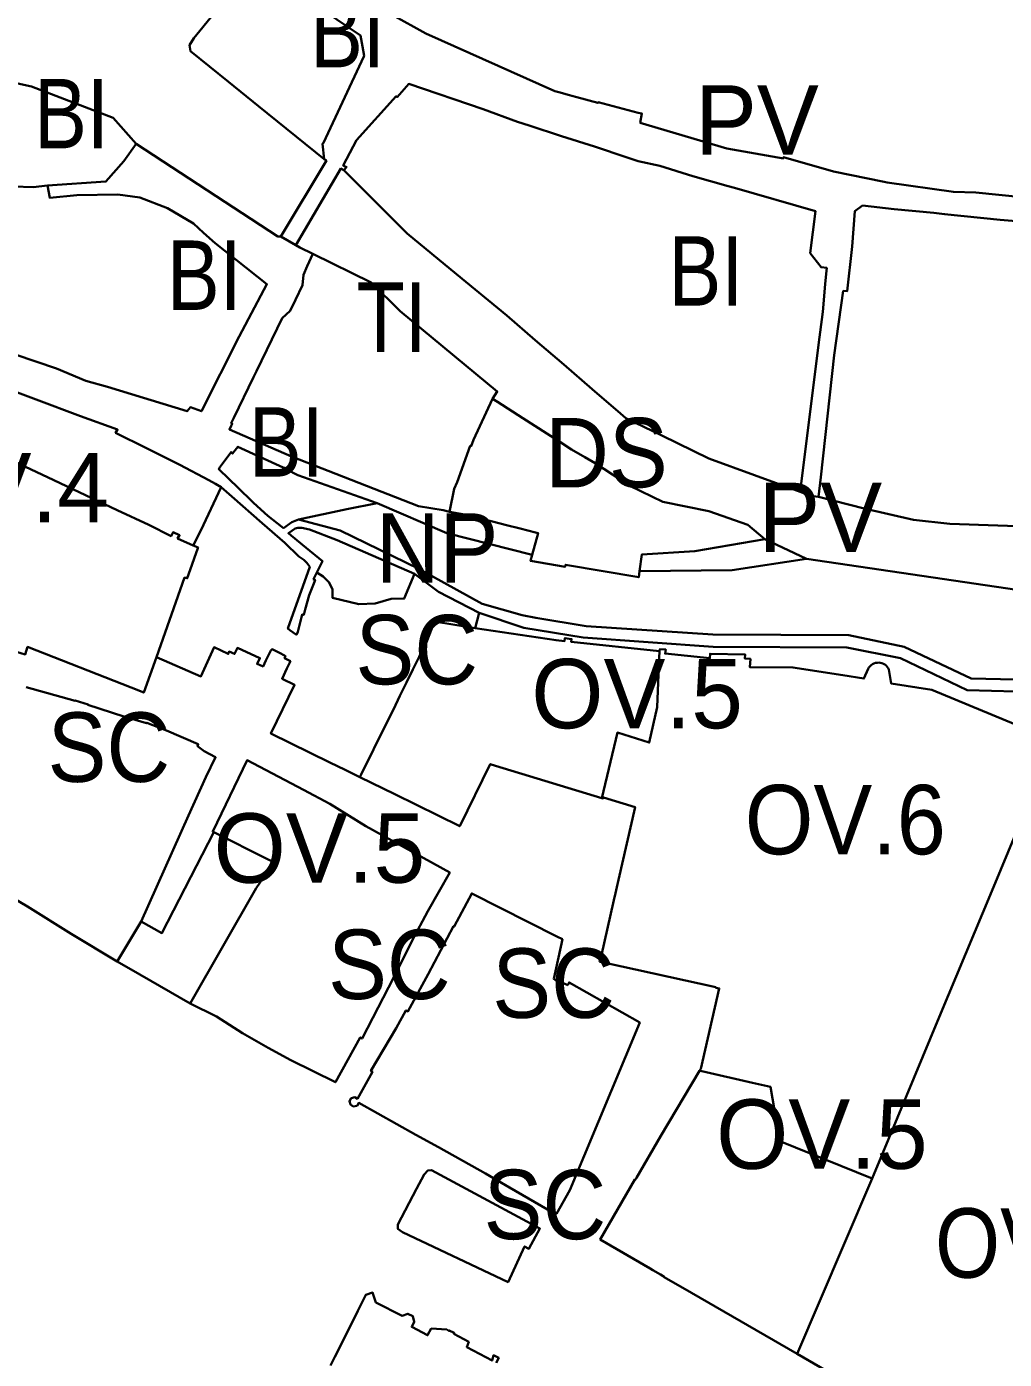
# Model space of a CAD drawing. Extents: x -650451 to -642268, y -1075216 to -1066610.
# Drawn here: x -647137 to -646925.8, y -1070596.5 to -1070308.6 of the extents above; entities that cross this region are included whole.
import ezdxf

# ---------------------------------------------------------------- set-up
doc = ezdxf.new("R2010")
doc.units = 0
doc.header["$LTSCALE"] = 6
doc.layers.add('1', color=7, linetype='Continuous', lineweight=35)
doc.layers.add('2', color=7, linetype='Continuous')
doc.layers.add('3', color=7, linetype='Continuous')

msp = doc.modelspace()

# ---------------------------------------------------------------- linework, layer by layer
at = {"layer": '1'}
for p, q in [((-647078.86, -1070355.81), (-647082.11, -1070353.97)), ((-646968.58, -1070423.58), (-646977.58, -1070419.35)), ((-647040.14, -1070438.54), (-647039.22, -1070435.22)), ((-647112.27, -1070501.93), (-647117.43, -1070510.56))]:
    msp.add_line(p, q, dxfattribs=at)
for points in [[(-647072.72, -1070337.21), (-647086.89, -1070325.79), (-647093.42, -1070320.51), (-647101.57, -1070313.94), (-647101.85, -1070312.63), (-647100.87, -1070311.13), (-647096.71, -1070305.97), (-647093.79, -1070301.88), (-647090.95, -1070296.93), (-647090.45, -1070297.18), (-647089.23, -1070294.23)], [(-647072.72, -1070337.21), (-647073.09, -1070333.91), (-647072.86, -1070333.71), (-647064.13, -1070315.05), (-647064.1, -1070314.92), (-647064.47, -1070312.9), (-647064.89, -1070310.53), (-647072.69, -1070305.26), (-647076.87, -1070302.51), (-647089.23, -1070294.23)], [(-647058.03, -1070306.03), (-647050.79, -1070310.08), (-647022.93, -1070322.52), (-647022.06, -1070322.76), (-647019.71, -1070323.4), (-647019.26, -1070323.53), (-647018.18, -1070323.82), (-647013.61, -1070325.08), (-647013.56, -1070324.94), (-647004.88, -1070327.21), (-647004.11, -1070327.41), (-647004.46, -1070329.4), (-646985.78, -1070334.95), (-646973.53, -1070337.09), (-646973.52, -1070336.83), (-646962.71, -1070339.87), (-646951.75, -1070342.15), (-646951.13, -1070342.27), (-646936.83, -1070344.32), (-646931.97, -1070344.46), (-646917.07, -1070345.99)], [(-647113.37, -1070333.96), (-647118.28, -1070328.29), (-647135.94, -1070321.54), (-647140.83, -1070320.47), (-647147.66, -1070321.04), (-647161.17, -1070326.29), (-647167.03, -1070329.81)], [(-647068.45, -1070339.63), (-647067.88, -1070338.96), (-647068.61, -1070338.61), (-647065.73, -1070333.17), (-647057.15, -1070323.66), (-647056.98, -1070323.84), (-647054.46, -1070321), (-647038.38, -1070326.41), (-647030.94, -1070329.17), (-647028.48, -1070329.97), (-647021.45, -1070332.25), (-647014.34, -1070334.53), (-647007.29, -1070336.87), (-647004.92, -1070337.65), (-647000.21, -1070338.68), (-646993.08, -1070340.92), (-646985.49, -1070343.05), (-646984.07, -1070343.44), (-646966.58, -1070348.48), (-646967.75, -1070357.53), (-646965.41, -1070360.58), (-646964.16, -1070360.72), (-646964.29, -1070362.04), (-646964.49, -1070364.27), (-646965.05, -1070370.23), (-646965.94, -1070377.32), (-646969.91, -1070409.14)], [(-647132.49, -1070342.91), (-647119.88, -1070342.1), (-647116.03, -1070337.68), (-647113.37, -1070333.96)], [(-647113.37, -1070333.96), (-647082.71, -1070353.92), (-647082.11, -1070353.97)], [(-647082.11, -1070353.97), (-647072.24, -1070337.5), (-647072.72, -1070337.21)], [(-647068.45, -1070339.63), (-647069.12, -1070339.27), (-647078.86, -1070355.81)], [(-646969.91, -1070409.14), (-646989.61, -1070401.88), (-646999.81, -1070396.94), (-647007.6, -1070393.17), (-647008.76, -1070392.17), (-647014.84, -1070386.9), (-647020.98, -1070381.63), (-647027.13, -1070376.32), (-647033.31, -1070370.98), (-647044.12, -1070362.09), (-647054.78, -1070353.33), (-647068.45, -1070339.63)], [(-647156.9, -1070372.69), (-647154.31, -1070363.46), (-647151.09, -1070353.15), (-647147.6, -1070341.95), (-647144.57, -1070342.42), (-647139.84, -1070343.16), (-647135.62, -1070343.32), (-647132.49, -1070342.91)], [(-647156.9, -1070372.69), (-647139.5, -1070379.46), (-647130.57, -1070382.45), (-647124.22, -1070385.16), (-647119.54, -1070386.4), (-647102.34, -1070391.7), (-647101.63, -1070390.83), (-647099.26, -1070391.68), (-647091.08, -1070375.52), (-647085.09, -1070364.27), (-647096.25, -1070355.36), (-647098.83, -1070353.16), (-647100.99, -1070351.16), (-647106.56, -1070347.82), (-647112.55, -1070345.53), (-647117.31, -1070344.9), (-647126.15, -1070345.04), (-647132, -1070345.56), (-647132.49, -1070342.91)], [(-646965.93, -1070410.19), (-646965.42, -1070405.95), (-646962.59, -1070379.57), (-646960.62, -1070365.71), (-646959.78, -1070365.76), (-646958.72, -1070356.13), (-646958.14, -1070348.48), (-646956.45, -1070347.28), (-646949.63, -1070348.01), (-646941.06, -1070348.87), (-646938.74, -1070349.11), (-646926.71, -1070350.38), (-646907.07, -1070352.03)], [(-647078.86, -1070355.81), (-647077.98, -1070356.31), (-647075.21, -1070357.69)], [(-647075.21, -1070357.69), (-647076.38, -1070360.33), (-647077.22, -1070362.23), (-647077.38, -1070364.46), (-647078.95, -1070367.66), (-647080.1, -1070369.99), (-647081.79, -1070371.62), (-647087.35, -1070383.02), (-647087.98, -1070384.3), (-647092.27, -1070393.14), (-647092.8, -1070394.26), (-647092.58, -1070394.38), (-647092.81, -1070394.84), (-647093.2, -1070395.61), (-647079.82, -1070401.44), (-647052.35, -1070412.19), (-647047.04, -1070413.1), (-647045.68, -1070413.42)], [(-647075.21, -1070357.69), (-647062.61, -1070363.91), (-647056.34, -1070370.1), (-647035.36, -1070387.44), (-647036.37, -1070389)], [(-647094.97, -1070408.13), (-647096.19, -1070407.37), (-647097.62, -1070406.58), (-647103.89, -1070403.25), (-647111.1, -1070399.66), (-647117.77, -1070396.35), (-647117.34, -1070395.66), (-647125.34, -1070392.73), (-647134.95, -1070389.15), (-647143.43, -1070386), (-647166.72, -1070377.36), (-647179.94, -1070372.43), (-647203.62, -1070364.76), (-647211.86, -1070363.44), (-647217.41, -1070363.66)], [(-647101, -1070420.71), (-647104.39, -1070419.17), (-647103.98, -1070418.49), (-647105.38, -1070417.82), (-647105.79, -1070418.65), (-647110.57, -1070416.24), (-647117.43, -1070413.03), (-647131.12, -1070406.58), (-647148.47, -1070398.43), (-647170.69, -1070388.11)], [(-647045.68, -1070413.42), (-647044.65, -1070408.45), (-647044.04, -1070406.99), (-647041.18, -1070399.14), (-647040.97, -1070399.22), (-647040.51, -1070397.9), (-647036.37, -1070389)], [(-646977.58, -1070419.35), (-646981.21, -1070416.23), (-646989.61, -1070413.31), (-646999.58, -1070411.3), (-647006.71, -1070407.79), (-647014.21, -1070402.89), (-647016.41, -1070401.61), (-647019.28, -1070399.95), (-647022.08, -1070398.15), (-647024.67, -1070396.5), (-647027.24, -1070394.85), (-647029.83, -1070393.19), (-647035.28, -1070389.69), (-647036.37, -1070389)], [(-647078.27, -1070415.07), (-647079.72, -1070415.69), (-647081.55, -1070416.92), (-647081.87, -1070416.67), (-647084.91, -1070414.32), (-647087.98, -1070411.47), (-647088.29, -1070411.18), (-647091.24, -1070408.34), (-647095.5, -1070404.2), (-647095.28, -1070403.79), (-647092.83, -1070400.52), (-647092.56, -1070400.86), (-647091.35, -1070399.37), (-647081.57, -1070403.84), (-647081.36, -1070403.95), (-647080.8, -1070404.25), (-647078.45, -1070405.49), (-647061.28, -1070411.53)], [(-647094.97, -1070408.13), (-647099.4, -1070417.47), (-647101, -1070420.71)], [(-647074.29, -1070426.5), (-647074.81, -1070427.56), (-647075.01, -1070427.99), (-647074.7, -1070428.16), (-647075.94, -1070431.43), (-647076.84, -1070434.5), (-647077.15, -1070435.7), (-647077.46, -1070435.57), (-647078.39, -1070439.33), (-647078.72, -1070439.98), (-647080.14, -1070439), (-647080.55, -1070438.64), (-647079.77, -1070436.42), (-647078.76, -1070433.56), (-647075.84, -1070425.31), (-647076.51, -1070424.44), (-647077.1, -1070423.78), (-647078.2, -1070423.04), (-647081.22, -1070420.13), (-647086.13, -1070415.86), (-647092.69, -1070410.13), (-647094.97, -1070408.13)], [(-646965.93, -1070410.19), (-646967.78, -1070409.96), (-646969.91, -1070409.14)], [(-646965.93, -1070410.19), (-646956.08, -1070412.71), (-646945.45, -1070415.18), (-646937.58, -1070416), (-646908.59, -1070417.04), (-646884.16, -1070418.2), (-646862.34, -1070418.49), (-646849.01, -1070416.7), (-646838.99, -1070415.41), (-646819.62, -1070412.61), (-646801.41, -1070411.72), (-646769.99, -1070409.89), (-646769.55, -1070409.87), (-646764.96, -1070409.6), (-646749.33, -1070408.07), (-646746.15, -1070407.76), (-646741.88, -1070407.34), (-646734.48, -1070408.27), (-646724.42, -1070408.21), (-646714.6, -1070407.67)], [(-647061.28, -1070411.53), (-647067.82, -1070412.86), (-647078.27, -1070415.07)], [(-647027.8, -1070422.73), (-647046.22, -1070418.03), (-647061.28, -1070411.53)], [(-647027.8, -1070422.73), (-647026.53, -1070418.01), (-647027.05, -1070417.88), (-647030.38, -1070417.03), (-647033.34, -1070416.28), (-647036.39, -1070415.52), (-647039.4, -1070414.76), (-647042.4, -1070414), (-647045.68, -1070413.42)], [(-647074.29, -1070426.5), (-647074, -1070425.92), (-647073.1, -1070424.08), (-647076.6, -1070421.22), (-647079.86, -1070418.55), (-647080.45, -1070418.06), (-647078.99, -1070417), (-647078.41, -1070416.9), (-647077.58, -1070416.88), (-647075.89, -1070417.25), (-647069.93, -1070419.52), (-647053.22, -1070426.8)], [(-646795.84, -1070457.11), (-646798.18, -1070457.17), (-646885.55, -1070454.3), (-646907.55, -1070449.99), (-646932.98, -1070449.44), (-646947.43, -1070442.59), (-646959.4, -1070440.06), (-646988.78, -1070439.92), (-647016.13, -1070438.11), (-647027.03, -1070436.35), (-647029.96, -1070435.73), (-647038.62, -1070433.3), (-647052.28, -1070425.72), (-647069.27, -1070417.46), (-647078.27, -1070415.07)], [(-647186.56, -1070420.18), (-647160.92, -1070434.39), (-647149.82, -1070439.78), (-647148.72, -1070440.26), (-647145.25, -1070441.23), (-647144.79, -1070441.36), (-647140.88, -1070442.51), (-647141.06, -1070443.08), (-647137.31, -1070444.24), (-647136.8, -1070442.59), (-647114.44, -1070451.37), (-647111.71, -1070452.49), (-647108.96, -1070444.81)], [(-647101, -1070420.71), (-647099.97, -1070421.15), (-647100.03, -1070421.31), (-647102.02, -1070426.93), (-647102.32, -1070427.77), (-647102.9, -1070427.62), (-647108.96, -1070444.81)], [(-647004.61, -1070426.22), (-647004.13, -1070422.66), (-646992.69, -1070421.92), (-646977.58, -1070419.35)], [(-647004.61, -1070426.22), (-647004.79, -1070427.57), (-647020.57, -1070424.86), (-647020.65, -1070425.28), (-647028.16, -1070424.03), (-647027.8, -1070422.73)], [(-646968.58, -1070423.58), (-646984.64, -1070426.01), (-647004.61, -1070426.22)], [(-646795.6, -1070423.94), (-646818.72, -1070427.14), (-646861.58, -1070431.99), (-646883.36, -1070431.36), (-646909.42, -1070432.29), (-646968.58, -1070423.58)], [(-647053.22, -1070426.8), (-647055.45, -1070432.17), (-647058.23, -1070432.25), (-647061.72, -1070433.22), (-647065.26, -1070433.38), (-647070.95, -1070432), (-647070.9, -1070430.16), (-647071.71, -1070428.63), (-647072.93, -1070427.37), (-647074.29, -1070426.5)], [(-647039.22, -1070435.22), (-647048.03, -1070430.69), (-647053.22, -1070426.8)], [(-647065, -1070470.75), (-647064.72, -1070470.17), (-647059.34, -1070459.24), (-647057.79, -1070456.1), (-647056.36, -1070453.17), (-647054.93, -1070450.26), (-647053.56, -1070447.48), (-647052.24, -1070444.75), (-647050.48, -1070441.24), (-647049.5, -1070438.66), (-647048.91, -1070437.12), (-647040.14, -1070438.54)], [(-646886.28, -1070456.9), (-646907.6, -1070452.64), (-646933.81, -1070451.94), (-646948.26, -1070445.04), (-646959.87, -1070442.73), (-646988.72, -1070442.62), (-647016.79, -1070440.55), (-647029.63, -1070438.51), (-647039.22, -1070435.22)], [(-647040.14, -1070438.54), (-647022.64, -1070441.16), (-647020.8, -1070441.35), (-647020.73, -1070440.71), (-647019.28, -1070440.91), (-647019.35, -1070441.51), (-647000.29, -1070443.55)], [(-647108.96, -1070444.81), (-647099.36, -1070448.97), (-647096.5, -1070442.67), (-647093.44, -1070444.11), (-647093.28, -1070443.63), (-647092.09, -1070444.12), (-647091.47, -1070442.83), (-647086.61, -1070445.01), (-647087.23, -1070446.27), (-647085.94, -1070446.83), (-647085.34, -1070445.57), (-647084.22, -1070443.4), (-647083.98, -1070443.1), (-647082.41, -1070443.92), (-647081.3, -1070444.49), (-647081.11, -1070444.59), (-647081.29, -1070445.06), (-647080.03, -1070445.69), (-647080.78, -1070447.28), (-647081.81, -1070449.47), (-647079.12, -1070450.83), (-647084.23, -1070461.32), (-647071.52, -1070467.55), (-647068.19, -1070469.19), (-647065, -1070470.75)], [(-647012.75, -1070475.28), (-647009.39, -1070461.13), (-647002.5, -1070463.29), (-647000.8, -1070455.61), (-647000.35, -1070445.01), (-647000.29, -1070443.55)], [(-647000.29, -1070443.55), (-647000.25, -1070443.1), (-646998.96, -1070443.2), (-646999.08, -1070444.05), (-646989.4, -1070445.07), (-646989.36, -1070444.1), (-646981.8, -1070444.21), (-646981.84, -1070445.12), (-646980.68, -1070445.19), (-646980.76, -1070447), (-646971.5, -1070447.04), (-646960.73, -1070448.7), (-646956.13, -1070449.46), (-646955.24, -1070447.37), (-646955.069, -1070447.078), (-646954.852, -1070446.804), (-646954.594, -1070446.559), (-646954.299, -1070446.352), (-646953.978, -1070446.189), (-646953.64, -1070446.077), (-646953.296, -1070446.014), (-646952.958, -1070446.001), (-646952.621, -1070446.034), (-646952.282, -1070446.116), (-646951.951, -1070446.248), (-646951.64, -1070446.429), (-646951.358, -1070446.653), (-646951.114, -1070446.913), (-646950.914, -1070447.198), (-646950.76, -1070447.5), (-646950.26, -1070450.53), (-646941.45, -1070451.87), (-646915.42, -1070462.65)], [(-647112.27, -1070501.93), (-647102.03, -1070479), (-647098.27, -1070470.75), (-647096.2, -1070466.44), (-647098.64, -1070465.11), (-647100.07, -1070464.06), (-647099.92, -1070463.63), (-647106.76, -1070460.66), (-647111.07, -1070458.98), (-647111.11, -1070459.1), (-647115.99, -1070457.62), (-647123.77, -1070455.11), (-647123.74, -1070455.03), (-647126.49, -1070454.16), (-647126.52, -1070454.24), (-647137.07, -1070451.29)], [(-646954.38, -1070557.43), (-646939.89, -1070522.56), (-646928.55, -1070495.36), (-646923.06, -1070482.21), (-646917.17, -1070467.11), (-646915.79, -1070463.58), (-646915.42, -1070462.65)], [(-647096.59, -1070482.6), (-647096.81, -1070482.49), (-647089.39, -1070467.1), (-647077.19, -1070473.5), (-647071.52, -1070476.47), (-647063.74, -1070481.33), (-647045.61, -1070491.35), (-647050.35, -1070499.67), (-647053.72, -1070506), (-647056.5, -1070511.72), (-647064.53, -1070527.22), (-647064.95, -1070526.98), (-647070.29, -1070536.65), (-647079.93, -1070531.89), (-647084.81, -1070529.22), (-647090.37, -1070526.04), (-647096, -1070522.46), (-647101.68, -1070519.61)], [(-647065, -1070470.75), (-647057.5, -1070474.44), (-647043.43, -1070481.34), (-647036.87, -1070467.93), (-647035.73, -1070468.27), (-647012.75, -1070475.28)], [(-647012.75, -1070475.28), (-647012.53, -1070475.35), (-647012.43, -1070475.12), (-647005.57, -1070477.19), (-647009.14, -1070492.92), (-647009.49, -1070494.49), (-647009.79, -1070495.77), (-647010.14, -1070497.33), (-647012.89, -1070509.45), (-647012.98, -1070509.45), (-647013.23, -1070510.59), (-647012.07, -1070510.91), (-647012.05, -1070510.82), (-646988.14, -1070516.12), (-646988.12, -1070516.22), (-646987.38, -1070516.38), (-646991.4, -1070533.77), (-646991.63, -1070534.15)], [(-647112.27, -1070501.93), (-647107.77, -1070504.44), (-647096.59, -1070482.6)], [(-647096.59, -1070482.6), (-647084.83, -1070488.5), (-647083.28, -1070489.27), (-647083.57, -1070489.75), (-647083.98, -1070489.83), (-647085.84, -1070492.4), (-647087.4, -1070494.74), (-647101.68, -1070519.61)], [(-647143.21, -1070494.91), (-647136.79, -1070498.68), (-647127.37, -1070504.6), (-647117.43, -1070510.56)], [(-647101.68, -1070519.61), (-647112.55, -1070513.38), (-647117.43, -1070510.56)], [(-646991.63, -1070534.15), (-646999.98, -1070548.21), (-647005.3, -1070557.33), (-647005.56, -1070557.72), (-647005.65, -1070557.68), (-647013.1, -1070570.62), (-647002.29, -1070576.9), (-647001.71, -1070577.23), (-647000.08, -1070578.18), (-646999.5, -1070578.52), (-646999.24, -1070578.67), (-646999.31, -1070578.78), (-646993.39, -1070582.12), (-646970.59, -1070595.31)], [(-646954.38, -1070557.43), (-646974.3, -1070549.38), (-646976.36, -1070537.64), (-646980.21, -1070536.81), (-646991.19, -1070534.26), (-646991.63, -1070534.15)], [(-646970.59, -1070595.31), (-646960.59, -1070571.95), (-646954.38, -1070557.43)], [(-647035.56, -1070597.27), (-647035.01, -1070596.21), (-647036.14, -1070595.63), (-647036.48, -1070596.79), (-647041.93, -1070593.87), (-647041.51, -1070592.73), (-647044.73, -1070590.99), (-647044.64, -1070590.79), (-647045.72, -1070590.25), (-647045.8, -1070590.38), (-647046.24, -1070590.07), (-647049.61, -1070589.85), (-647050.39, -1070591.32), (-647053.83, -1070589.49), (-647053.26, -1070588.38), (-647053.57, -1070587.2), (-647054.64, -1070586.65), (-647055.92, -1070587.1), (-647061.55, -1070584.24), (-647062.29, -1070582.1), (-647063.75, -1070582.54), (-647065.48, -1070586.02), (-647066.86, -1070588.81), (-647070.42, -1070595.98), (-647071.34, -1070597.83)], [(-646970.59, -1070595.31), (-646965.61, -1070598.2), (-646962.81, -1070599.83), (-646951.58, -1070606.31), (-646951.78, -1070606.66), (-646948.18, -1070608.65), (-646948, -1070608.33), (-646936.83, -1070615.01), (-646936.61, -1070614.62), (-646928.86, -1070618.91), (-646911.17, -1070626.24), (-646907.97, -1070620.52), (-646907.24, -1070620.87)]]:
    msp.add_lwpolyline(points, dxfattribs=at)
for points in [[(-647020.1, -1070515.66), (-647022.32, -1070514.69), (-647022.38, -1070514.85), (-647023.16, -1070514.31), (-647021.26, -1070505.75), (-647022.49, -1070505.18), (-647040.86, -1070495.87), (-647044.63, -1070503.01), (-647044.79, -1070502.93), (-647050.27, -1070513.3), (-647054.64, -1070521.33), (-647055.06, -1070521.12), (-647057.15, -1070524.97), (-647062.65, -1070534.18), (-647062.32, -1070534.39), (-647065.56, -1070540.21), (-647066.14, -1070539.9), (-647066.9, -1070540.09), (-647067.27, -1070540.75), (-647067.03, -1070541.49), (-647066.44, -1070541.88), (-647065.63, -1070541.73), (-647065.26, -1070541.11), (-647052.93, -1070547.98), (-647048.06, -1070550.69), (-647037.85, -1070556.38), (-647032.67, -1070559.38), (-647023.12, -1070564.9), (-647023.06, -1070564.77), (-647022.57, -1070565.05), (-647019.68, -1070559.99), (-647004.55, -1070523.77), (-647019.84, -1070515.08)], [(-647055.79, -1070569.07), (-647033.01, -1070579.83), (-647029.44, -1070572.13), (-647028.52, -1070572.63), (-647026.14, -1070568.26), (-647049.52, -1070555.64), (-647050.37, -1070555.74), (-647051.14, -1070556.59), (-647052.77, -1070559.7), (-647056.79, -1070567.41), (-647056.8, -1070568.32)]]:
    msp.add_lwpolyline(points, close=True, dxfattribs=at)

# ---------------------------------------------------------------- texts
at = {"layer": '2'}
for s, width, p in [('BI', 0.85, (-647075.746, -1070317.39)), ('BI', 0.85, (-646998.326, -1070368.88)), ('BI', 0.85, (-647106.676, -1070369.805)), ('TI', 0.85, (-647065.743, -1070378.88)), ('BI', 0.85, (-647088.988, -1070405.829)), ('DS', 0.95, (-647024.996, -1070408.146)), ('NP', 0.95, (-647061.575, -1070428.758)), ('SC', 0.95, (-647065.976, -1070450.694)), ('SC', 0.95, (-647132.475, -1070471.759)), ('OV.6', 0.95, (-646981.875, -1070487.411)), ('SC', 0.95, (-647071.887, -1070518.672)), ('SC', 0.95, (-647036.42, -1070522.736)), ('OV.1', 0.9, (-646940.776, -1070578.871))]:
    msp.add_text(s, height=15, dxfattribs=dict(at, width=width)).set_placement(p)
for s, p in [('PV', (-646992.649, -1070336.296)), ('OV.4', (-647164.92, -1070415.71)), ('PV', (-646978.97, -1070422.129)), ('OV.5', (-647027.997, -1070460.19)), ('OV.5', (-647096.61, -1070493.55)), ('OV.5', (-646988.076, -1070555.351))]:
    msp.add_text(s, height=15, dxfattribs=at).set_placement(p)
at = {"layer": '3'}
for s, width, p in [('BI', 0.85, (-647135.359, -1070334.904)), ('SC', 0.95, (-647038.292, -1070570.555))]:
    msp.add_text(s, height=15, dxfattribs=dict(at, width=width)).set_placement(p)

doc.saveas('drawing.dxf')
